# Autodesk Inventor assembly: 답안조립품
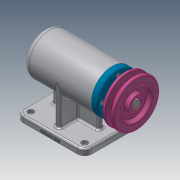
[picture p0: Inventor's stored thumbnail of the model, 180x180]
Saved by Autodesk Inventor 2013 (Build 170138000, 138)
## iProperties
Created: 2020-10
Part Number: 답안조립품
Document SubType Name: Assembly
Designer: 88
Author: 88
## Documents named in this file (12)
- C:\Users\88\Desktop\701004V1027\답안조립품.iam
- C:\Users\88\Desktop\701004V1027\본체.ipt
- C:\Users\88\Desktop\701004V1027\V벨트풀리.ipt
- C:\Users\88\Desktop\701004V1027\멈춤나사 M3.ipt
- C:\Users\88\Desktop\701004V1027\베어링 6004.ipt
- C:\Users\88\Desktop\701004V1027\베어링 51202.ipt
- C:\Users\88\Desktop\701004V1027\볼트 M4.ipt
- C:\Users\88\Desktop\701004V1027\어댑터슬리브.ipt
- C:\Users\88\Desktop\701004V1027\오일 실.ipt
- C:\Users\88\Desktop\701004V1027\축.ipt
- C:\Users\88\Desktop\701004V1027\커버.ipt
- C:\Users\88\Desktop\701004V1027\키 5 x 5 x 16.ipt
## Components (1 placed, 1 different names)
1. V벨트풀리:1 — 플러쉬:1
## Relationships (1: Flush 1)
- 플러쉬:1 [Flush]: V벨트풀리:1
